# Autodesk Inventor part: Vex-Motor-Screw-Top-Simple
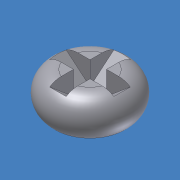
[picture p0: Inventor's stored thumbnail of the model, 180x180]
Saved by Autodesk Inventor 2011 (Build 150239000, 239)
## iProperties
Created: 2007-08
Part Number: Vex-Motor-Screw-Top-Simple
Material: Steel, Mild
Document SubType Name: Modeling
Density: 7.86 g/cm^3
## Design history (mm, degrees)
feature "Base1"
body "Solid1"
